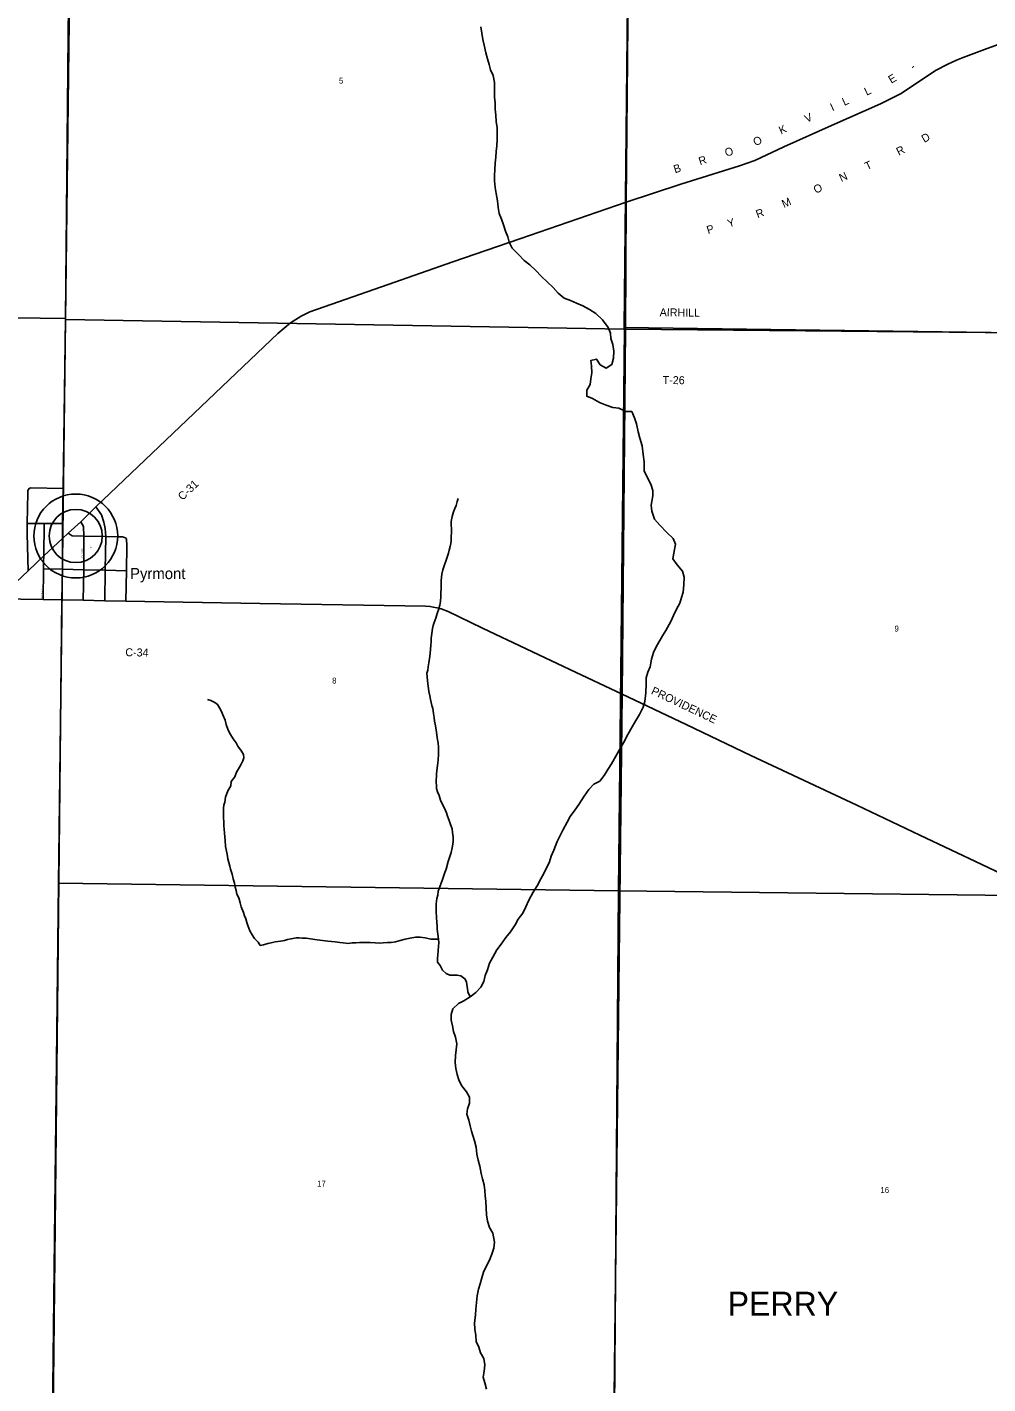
# Model space of a CAD drawing. Extents: x 1312308 to 1684953, y 460642 to 865172.
# Drawn here: x 1417251 to 1426256, y 657978 to 670697 of the extents above; entities that cross this region are included whole.
import ezdxf

# ---------------------------------------------------------------- set-up
doc = ezdxf.new("R2010")
doc.units = 0
for name, color, linetype in [('GM_X_County_Road', 7, 'Continuous'), ('GM_X_County_Road_Text', 7, 'Continuous'), ('GM_X_Minor_River', 7, 'Continuous'), ('GM_X_Section', 7, 'Continuous'), ('GM_X_Section_Text', 7, 'Continuous'), ('GM_X_Township_Road', 7, 'Continuous'), ('GM_X_Township_Road_Text', 7, 'Continuous'), ('GM_X_Township_Subdivision', 7, 'Continuous'), ('GM_X_Township_Subdivision_Text', 7, 'Continuous'), ('GM_X_Township_Text', 7, 'Continuous'), ('GM_X_Unincorporated', 7, 'Continuous'), ('GM_X_Unincorporated_Location', 7, 'Continuous'), ('GM_X_Unincorporated_Text', 7, 'Continuous')]:
    doc.layers.add(name, color=color, linetype=linetype)

msp = doc.modelspace()

# ---------------------------------------------------------------- linework, layer by layer
at = {"layer": 'GM_X_County_Road'}
for points in [[(1417576, 665329), (1417582, 665616), (1417582, 665904), (1417582, 666043), (1417588, 666373), (1417610, 667967), (1417635, 670624), (1417662, 672772), (1417276, 672769)], [(1422867, 669058), (1422900, 672752)], [(1416981, 665337), (1417260, 665600), (1417407, 665742), (1417582, 665904), (1417637, 665952), (1417753, 666061), (1417895, 666199), (1419209, 667454), (1419601, 667826), (1419720, 667925), (1419819, 667988), (1419901, 668029), (1420635, 668284), (1421242, 668496), (1421871, 668713), (1422867, 669058), (1423379, 669224), (1423927, 669396), (1424072, 669447), (1424345, 669576), (1424790, 669776), (1425251, 669979), (1425444, 670075), (1425766, 670290), (1425880, 670350), (1425962, 670389), (1426025, 670414), (1426225, 670487), (1426627, 670636)], [(1421357, 641492), (1421375, 642609), (1421384, 643489), (1421399, 644427), (1421401, 644460), (1421405, 644509), (1421413, 644552), (1421425, 644593), (1421442, 644632), (1421852, 645600), (1422342, 646771), (1422597, 647365), (1422605, 647390), (1422614, 647422), (1422618, 647451), (1422634, 648247), (1422675, 652042), (1422706, 654222), (1422749, 657312), (1422828, 664443), (1422860, 667867), (1422867, 669058)], [(1411429, 665387), (1416981, 665337), (1417400, 665332), (1417576, 665329)], [(1417302, 641536), (1417290, 641681), (1417317, 644162), (1417326, 644619), (1417353, 646822), (1417402, 649650), (1417410, 650593), (1417430, 652114), (1417492, 657404), (1417576, 665329)], [(1417576, 665329), (1417576, 665329), (1417777, 665324), (1417979, 665319), (1418176, 665315), (1419432, 665294), (1420985, 665268), (1421029, 665265), (1421058, 665260), (1421093, 665254), (1421132, 665245), (1421199, 665218), (1421518, 665062), (1422337, 664676), (1422828, 664443), (1423428, 664160), (1424036, 663868), (1425028, 663402), (1425226, 663310), (1425619, 663123), (1426201, 662847), (1426719, 662600)]]:
    msp.add_lwpolyline(points, dxfattribs=at)
at = {"layer": 'GM_X_Minor_River'}
for points in [[(1423107, 666160), (1423101, 666217), (1423117, 666305), (1423115, 666355), (1423097, 666414), (1423061, 666486), (1423034, 666539), (1423035, 666623), (1423025, 666692), (1423015, 666773), (1422993, 666844), (1422979, 666904), (1422963, 666979), (1422945, 667036), (1422918, 667095), (1422862, 667095), (1422796, 667125), (1422740, 667133), (1422679, 667153), (1422615, 667177), (1422552, 667215), (1422496, 667237), (1422496, 667293), (1422530, 667346), (1422535, 667401), (1422543, 667457), (1422541, 667521), (1422534, 667571), (1422587, 667586), (1422624, 667531), (1422679, 667501), (1422731, 667535), (1422749, 667595), (1422751, 667659), (1422742, 667722), (1422724, 667779), (1422718, 667829), (1422697, 667882), (1422643, 667954), (1422582, 668012), (1422521, 668050), (1422460, 668084), (1422400, 668110), (1422343, 668134), (1422285, 668156), (1422230, 668204), (1422181, 668256), (1422128, 668308), (1422070, 668362), (1422019, 668416), (1421964, 668470), (1421911, 668511), (1421857, 668567), (1421798, 668626), (1421770, 668681), (1421757, 668731), (1421735, 668786), (1421716, 668845), (1421698, 668896), (1421677, 668951), (1421665, 669008), (1421659, 669070), (1421649, 669139), (1421638, 669195), (1421632, 669256), (1421632, 669308), (1421636, 669362), (1421639, 669421), (1421645, 669479), (1421649, 669533), (1421655, 669585), (1421658, 669643), (1421658, 669699), (1421656, 669754), (1421647, 669812), (1421643, 669873), (1421639, 669929), (1421637, 669988), (1421632, 670040), (1421631, 670124), (1421633, 670179), (1421621, 670243), (1421594, 670296), (1421583, 670347), (1421567, 670400), (1421551, 670455), (1421535, 670527), (1421524, 670580), (1421512, 670641), (1421504, 670701)], [(1421136, 665542), (1421138, 665570), (1421147, 665610), (1421163, 665656), (1421175, 665690), (1421188, 665730), (1421201, 665766), (1421208, 665793), (1421217, 665827), (1421224, 665857), (1421226, 665885), (1421229, 665996), (1421226, 666030), (1421227, 666062), (1421234, 666110), (1421249, 666154), (1421260, 666184), (1421272, 666213), (1421283, 666249), (1421292, 666277)], [(1421459, 660196), (1421443, 660257), (1421417, 660346), (1421403, 660398), (1421390, 660449), (1421372, 660506), (1421378, 660558), (1421399, 660610), (1421397, 660666), (1421370, 660717), (1421324, 660775), (1421297, 660830), (1421281, 660880), (1421270, 660935), (1421264, 660991), (1421266, 661058), (1421272, 661110), (1421280, 661166), (1421265, 661229), (1421249, 661281), (1421237, 661336), (1421226, 661387), (1421226, 661441), (1421243, 661495), (1421295, 661543), (1421346, 661570), (1421404, 661608), (1421458, 661647), (1421505, 661698), (1421533, 661751), (1421545, 661807), (1421565, 661861), (1421585, 661922), (1421615, 661980), (1421653, 662047), (1421695, 662100), (1421739, 662163), (1421783, 662216), (1421825, 662283), (1421853, 662334), (1421897, 662391), (1421927, 662451), (1421955, 662512), (1421996, 662589), (1422032, 662648), (1422066, 662714), (1422096, 662769), (1422148, 662872), (1422163, 662924), (1422189, 662981), (1422218, 663063), (1422248, 663118), (1422272, 663170), (1422312, 663243), (1422342, 663296), (1422384, 663357), (1422422, 663409), (1422471, 663487), (1422517, 663550), (1422563, 663601), (1422618, 663628), (1422660, 663683), (1422694, 663738), (1422728, 663791), (1422770, 663862), (1422809, 663934), (1422842, 663987), (1422881, 664066), (1422922, 664139), (1422958, 664196), (1422991, 664252), (1423024, 664321), (1423042, 664375), (1423052, 664457), (1423053, 664541), (1423055, 664598), (1423068, 664649), (1423092, 664701), (1423104, 664771), (1423122, 664835), (1423148, 664888), (1423208, 664991), (1423239, 665042), (1423284, 665125), (1423310, 665181), (1423338, 665240), (1423368, 665296), (1423384, 665350), (1423399, 665401), (1423408, 665470), (1423410, 665540), (1423395, 665597), (1423345, 665656), (1423304, 665712), (1423312, 665766), (1423329, 665850), (1423306, 665903), (1423248, 665959), (1423181, 666029), (1423131, 666085), (1423107, 666160)], [(1421404, 661608), (1421382, 661654), (1421379, 661686), (1421374, 661720), (1421368, 661748), (1421355, 661777), (1421318, 661804), (1421280, 661811), (1421240, 661810), (1421212, 661810), (1421178, 661825), (1421145, 661858), (1421122, 661901), (1421099, 661931), (1421097, 661968), (1421100, 662002), (1421105, 662038), (1421108, 662082), (1421109, 662114), (1421106, 662148), (1421096, 662240), (1421095, 662270), (1421092, 662303), (1421089, 662355), (1421086, 662403), (1421085, 662443), (1421086, 662479), (1421091, 662529), (1421100, 662559), (1421103, 662597), (1421133, 662671), (1421144, 662707), (1421165, 662772), (1421178, 662802), (1421198, 662874), (1421211, 662912), (1421226, 662959), (1421235, 663005), (1421242, 663037), (1421245, 663067), (1421244, 663107), (1421239, 663148), (1421234, 663182), (1421221, 663222), (1421206, 663261), (1421192, 663299), (1421183, 663332), (1421162, 663374), (1421143, 663417), (1421126, 663451), (1421113, 663494), (1421098, 663530), (1421089, 663559), (1421087, 663589), (1421086, 663617), (1421088, 663697), (1421095, 663753), (1421101, 663797), (1421103, 663829), (1421107, 663877), (1421107, 663907), (1421106, 663948), (1421105, 663986), (1421096, 664036), (1421088, 664089), (1421081, 664127), (1421076, 664163), (1421070, 664191), (1421067, 664224), (1421060, 664264), (1421053, 664310), (1421044, 664338), (1421033, 664395), (1421026, 664429), (1421017, 664468), (1421014, 664498), (1421007, 664542), (1421000, 664606), (1420999, 664641), (1421006, 664669), (1421011, 664701), (1421016, 664739), (1421023, 664778), (1421030, 664824), (1421033, 664867), (1421036, 664901), (1421037, 664937), (1421039, 664969), (1421044, 665013), (1421050, 665059), (1421058, 665089), (1421067, 665117), (1421082, 665158), (1421095, 665200), (1421110, 665244), (1421119, 665280), (1421126, 665316), (1421129, 665356), (1421132, 665472), (1421133, 665508), (1421136, 665542)], [(1418972, 664386), (1418942, 664395)], [(1421106, 662148), (1421036, 662148), (1420982, 662159), (1420936, 662166), (1420890, 662165), (1420840, 662158), (1420795, 662146), (1420749, 662135), (1420705, 662122), (1420663, 662117), (1420628, 662116), (1420588, 662113), (1420554, 662111), (1420514, 662112), (1420466, 662116), (1420430, 662116), (1420402, 662117), (1420368, 662116), (1420332, 662113), (1420298, 662112), (1420260, 662107), (1420212, 662112), (1420182, 662117), (1420138, 662122), (1420104, 662126), (1420070, 662129), (1420020, 662135), (1419970, 662142), (1419866, 662156), (1419830, 662157), (1419802, 662160), (1419774, 662159), (1419726, 662152), (1419692, 662145), (1419664, 662135), (1419625, 662128), (1419577, 662121), (1419539, 662114), (1419507, 662107), (1419466, 662094), (1419436, 662089), (1419417, 662119), (1419382, 662154), (1419360, 662187), (1419339, 662226), (1419320, 662276), (1419309, 662305), (1419300, 662337), (1419289, 662367), (1419279, 662396), (1419257, 662450), (1419248, 662489), (1419235, 662535), (1419218, 662568), (1419210, 662602), (1419201, 662634), (1419194, 662673), (1419183, 662713), (1419172, 662757), (1419159, 662804), (1419152, 662832), (1419143, 662866), (1419132, 662901), (1419125, 662943), (1419110, 663016), (1419106, 663072), (1419103, 663108), (1419100, 663142), (1419098, 663179), (1419095, 663211), (1419094, 663241), (1419091, 663291), (1419091, 663347), (1419093, 663375), (1419096, 663405), (1419103, 663433), (1419110, 663477), (1419131, 663539), (1419161, 663586), (1419165, 663624), (1419197, 663670), (1419214, 663714), (1419241, 663761), (1419258, 663789), (1419274, 663818), (1419281, 663848), (1419278, 663878), (1419261, 663909), (1419226, 663958), (1419209, 663989), (1419181, 664025), (1419156, 664066), (1419137, 664107), (1419117, 664159), (1419106, 664200), (1419087, 664250), (1419074, 664281), (1419054, 664315), (1419037, 664348), (1419010, 664367), (1418972, 664386)], [(1421556, 657929), (1421542, 657989), (1421525, 658042), (1421535, 658098), (1421541, 658156), (1421531, 658215), (1421500, 658270), (1421484, 658321), (1421461, 658377), (1421457, 658432), (1421449, 658492), (1421446, 658549), (1421455, 658621), (1421457, 658679), (1421462, 658741), (1421471, 658805), (1421482, 658865), (1421498, 658917), (1421514, 658973), (1421528, 659026), (1421553, 659080), (1421585, 659137), (1421607, 659195), (1421627, 659252), (1421631, 659308), (1421615, 659391), (1421585, 659445), (1421567, 659505), (1421558, 659562), (1421554, 659628), (1421552, 659689), (1421546, 659741), (1421541, 659791), (1421535, 659844), (1421520, 659901), (1421506, 659951), (1421496, 660018), (1421479, 660075), (1421467, 660133), (1421459, 660196)]]:
    msp.add_lwpolyline(points, dxfattribs=at)
at = {"layer": 'GM_X_Section'}
for points in [[(1422589, 672759), (1422897, 672759), (1422848, 667882), (1422850, 667866), (1417610, 667958), (1417669, 672779)], [(1427885, 672758), (1428185, 672759), (1428122, 667809), (1422848, 667882), (1422897, 672759)], [(1417610, 667958), (1422850, 667866), (1422795, 662601), (1417546, 662672)], [(1422850, 667866), (1422848, 667882), (1428122, 667809), (1428085, 662539), (1422795, 662601)], [(1422795, 662601), (1422753, 657328), (1417487, 657391), (1417546, 662672)], [(1428085, 662539), (1428048, 657284), (1422753, 657328), (1422795, 662601)]]:
    msp.add_lwpolyline(points, close=True, dxfattribs=at)
at = {"layer": 'GM_X_Township_Road'}
for points in [[(1411445, 668019), (1414512, 668006), (1417610, 667967)], [(1422860, 667867), (1426568, 667832), (1428144, 667819), (1430264, 667830), (1432874, 667834)]]:
    msp.add_lwpolyline(points, dxfattribs=at)
at = {"layer": 'GM_X_Township_Subdivision'}
for points in [[(1417260, 665600), (1417253, 665948), (1417253, 666045), (1417258, 666331), (1417259, 666352), (1417270, 666373), (1417286, 666377), (1417588, 666373)], [(1417979, 665319), (1417982, 665606), (1417989, 665921), (1417982, 665997), (1417969, 666056), (1417948, 666126), (1417895, 666199)], [(1417253, 666045), (1417412, 666045), (1417582, 666043)], [(1417406, 665689), (1417407, 665742), (1417412, 666045)], [(1417777, 665324), (1417782, 665611), (1417782, 665924), (1417778, 666016), (1417767, 666038), (1417753, 666061)], [(1417637, 665952), (1417674, 665928), (1417782, 665924), (1417989, 665921), (1418101, 665919), (1418145, 665919), (1418172, 665911), (1418183, 665896), (1418186, 665839), (1418184, 665599), (1418176, 665315)], [(1417400, 665332), (1417405, 665619), (1417406, 665689)], [(1417405, 665619), (1417582, 665616), (1417782, 665611), (1417982, 665606), (1418184, 665599)]]:
    msp.add_lwpolyline(points, dxfattribs=at)
at = {"layer": 'GM_X_Unincorporated'}
for radius in [393, 249]:
    msp.add_circle((1417707, 665927), radius, dxfattribs=at)
at = {"layer": 'GM_X_Unincorporated_Location'}
msp.add_line((1417707, 665927), (1417707, 665927), dxfattribs=at)

# ---------------------------------------------------------------- texts
at = {"layer": 'GM_X_County_Road_Text'}
for s, rotation, p in [('-', 34.0627, (1425558, 670291)), ('E', 30.9633, (1425351, 670166)), ('L', 25.3748, (1425120, 670054)), ('I', 24.4587, (1424799, 669908)), ('L', 24.4664, (1424911, 669959)), ('V', 24.4578, (1424559, 669799)), ('O', 24.3709, (1424077, 669581)), ('K', 24.4578, (1424318, 669690)), ('D', 30.1233, (1425661, 669611)), ('O', 19.9246, (1423806, 669481)), ('R', 26.3665, (1425421, 669492)), ('B', 17.6333, (1423324, 669327)), ('R', 17.6875, (1423559, 669402)), ('T', 24.6388, (1425124, 669354)), ('N', 24.5111, (1424883, 669245)), ('O', 24.4834, (1424643, 669135)), ('M', 24.3, (1424345, 669001)), ('Y', 17.6535, (1423829, 668818)), ('R', 21.2021, (1424099, 668905)), ('P', 17.4297, (1423634, 668757)), ('C-31', 43.7808, (1418708, 666256)), ('C-34', 358.9701, (1418171, 664800)), ('PROVIDENCE', 334.6951, (1423094, 664450))]:
    msp.add_text(s, height=75, rotation=rotation, dxfattribs=at).set_placement(p)
at = {"layer": 'GM_X_Section_Text'}
for s, p in [('5', (1420174, 670168)), ('9', (1425381, 665031)), ('8', (1420110, 664544)), ('17', (1419969, 659828)), ('16', (1425249, 659768))]:
    msp.add_text(s, height=55.3, rotation=0, dxfattribs=at).set_placement(p)
at = {"layer": 'GM_X_Township_Road_Text'}
for s, rotation, p in [('AIRHILL', 359.3122, (1423180, 667987)), ('T-26', 359.2931, (1423208, 667352))]:
    msp.add_text(s, height=75, rotation=rotation, dxfattribs=at).set_placement(p)
at = {"layer": 'GM_X_Township_Subdivision_Text'}
for s, p in [('HARKERS', (1417771, 665726)), ('ALY', (1417857, 665809)), ('WEST ALY', (1417397, 665343))]:
    msp.add_text(s, height=12.5, rotation=90, dxfattribs=at).set_placement(p)
at = {"layer": 'GM_X_Township_Text'}
msp.add_text('PERRY', height=225, rotation=0, dxfattribs=at).set_placement((1423817, 658617))
at = {"layer": 'GM_X_Unincorporated_Text'}
msp.add_text('Pyrmont', height=104.3, rotation=0, dxfattribs=at).set_placement((1418216, 665523))

doc.saveas('drawing.dxf')
